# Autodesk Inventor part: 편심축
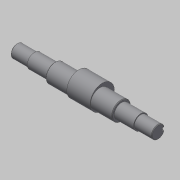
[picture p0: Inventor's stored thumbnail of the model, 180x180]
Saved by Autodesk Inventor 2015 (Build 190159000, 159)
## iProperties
Created: 2015-10
Part Number: 편심축
Document SubType Name: Modeling
Designer: mdu
Density: 1 g/cm^3
Material: 일반
Mass: 168.947 g
Surface Area: 248.524 cm^2
Volume: 168.947 cm^3
Appearance: 기본값
Author: mdu
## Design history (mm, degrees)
sketch "스케치1"
  geometry: L1 (-20.5, -41.331)-(-20.5, 32.669) reference; L2 (7.5, -30.031)-(7.5, 21.369) reference; L3 (135.5, -30.331)-(135.5, 21.669) reference; L4 (121.5, 21.369)-(121.5, -30.031) reference; L5 (184.5, -4.331)-(-57.5, -4.331); L6 (184.5, -4.331)-(184.5, 6.669); L7 (154.5, 8.169)-(121.5, 8.169); L8 (121.5, 8.169)-(121.5, 11.669); L9 (121.5, 11.669)-(7.5, 11.669); L10 (7.5, 11.669)-(7.5, 8.169); L11 (7.5, 8.169)-(-27.5, 8.169); L12 (-27.5, 8.169)-(-27.5, 6.669); L13 (-27.5, 6.669)-(-57.5, 6.669); L14 (-57.5, 6.669)-(-57.5, -4.331); L15 (154.5, 8.169)-(154.5, 6.669); L16 (154.5, 6.669)-(184.5, 6.669); C1 r 32.5 at (64.5, -4.331) reference; 1 further point
  constraints: 24 end point, 8 perpendicular, 5 point on line, 3 parallel, 2 collinear
  dimensions: "d1" = 25 diameter of L11 L5; "d2" = 32 diameter of L9 L5; "d3" = 22 diameter of L13 L5; "d4" = 35 distance of L10.end L11.end; "d5" = 30 distance of L12.end L13.end; "d15" = 33 distance of L7.start L7.end; "d26" = 30 distance of L15.end L6.end
revolve "회전1" sketch "스케치1" stored, may be unused: angle "d6" = 90 deg
node "작업 평면1"
sketch "스케치2"
  geometry: C1 r 16 at (0, 0) reference; C2 r 16 at (0, 0) reference; C3 r 20.75 at (0, 4); C4 r 16 at (0, 0) reference; 1 further point
  constraints: 1 centre point, 1 vertical alignment
  dimensions: "d8" = 41.5 diameter of C3; "d25" = 4 distance of C3.centre C1.centre
extrude "돌출1" join sketch "스케치2" stored distance "d9" = 40; taper "d10" = 0 deg
chamfer "모따기1" distance "d11" = 1; stored, may be unused: second distance "d12" = 2, angle "d13" = 45 deg
node "작업 평면2"
sketch "스케치3"
  geometry: L1 (-15, -10)-(-15, 10) reference; L2 (-15, 3)-(0, 3); L3 (0, -3)-(-15, -3); A1 r 3 centre (0, 0) between (0, -3) and (0, 3); 2 further points
  constraints: 4 end point, 2 perpendicular, 2 point on circle, 2 point on line, 2 tangent, 1 centre point, 1 horizontal alignment, 1 midpoint
  dimensions: "d16" = 18 dimension on A1 L1; "d17" = 6 distance between parallel lines of L3 L2
extrude "돌출2" cut sketch "스케치3" distance "d18" = 3.5; taper "d19" = 0 deg
node "작업 평면3"
node "솔리드1"
mirror "대칭1"
node "참조1"
node "참조2"
node "참조3"
node "참조4"
node "참조5"
node "투영된 루프1"
